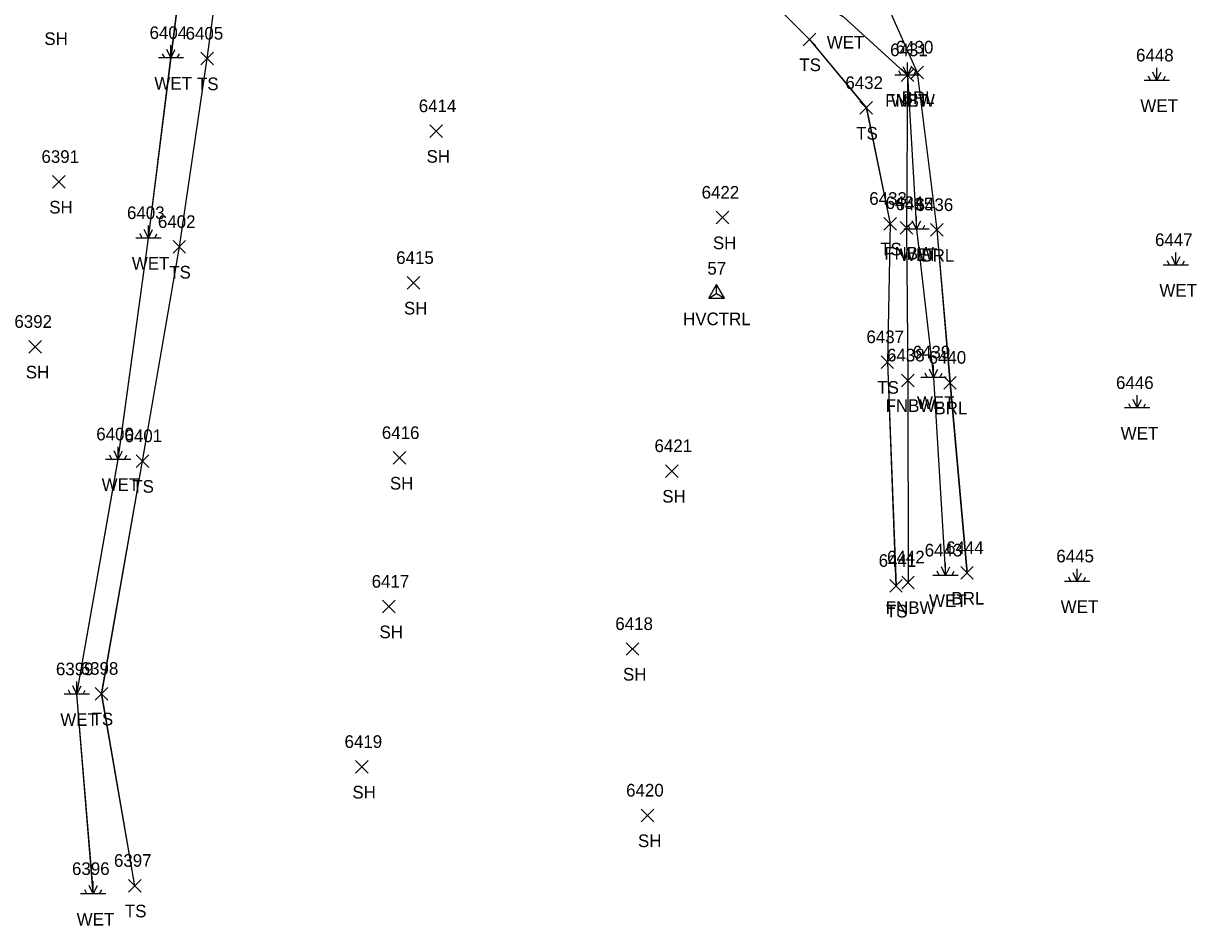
# Model space of a CAD drawing. Extents: x 1554668 to 1563881, y 831386 to 834374.
# Drawn here: x 1563328.7 to 1563514.3, y 833786 to 833928.7 of the extents above; entities that cross this region are included whole.
import ezdxf

# ---------------------------------------------------------------- set-up
doc = ezdxf.new("R2010")
doc.units = 0
for name, color, linetype in [('C_A', 7, 'Continuous'), ('C_I', 7, 'Continuous'), ('CPSM', 7, 'Continuous'), ('L_A', 7, 'Continuous'), ('L_I', 7, 'Continuous'), ('L_TIC', 7, 'Continuous'), ('LABL', 7, 'Continuous'), ('LELB', 7, 'Continuous'), ('LFNC', 7, 'Continuous'), ('LWET', 7, 'Continuous')]:
    doc.layers.add(name, color=color, linetype=linetype)

msp = doc.modelspace()

# ---------------------------------------------------------------- linework, layer by layer
at = {"layer": 'CPSM'}
for p, q in [((1563437.12, 833885.21), (1563438.37, 833887.38)), ((1563439.62, 833885.21), (1563438.37, 833887.38)), ((1563438.37, 833885.93), (1563438.37, 833887.38)), ((1563437.12, 833885.21), (1563438.37, 833885.93)), ((1563438.37, 833885.93), (1563438.37, 833885.93)), ((1563438.37, 833885.93), (1563439.62, 833885.21)), ((1563437.12, 833885.21), (1563439.62, 833885.21))]:
    msp.add_line(p, q, dxfattribs=at)
at = {"layer": 'L_TIC'}
for points in [[(1563452.05, 833925.12), (1563454.05, 833927.12)], [(1563454.05, 833925.12), (1563452.05, 833927.12)], [(1563356.77, 833922.1), (1563358.77, 833924.1)], [(1563358.77, 833922.1), (1563356.77, 833924.1)], [(1563467.56, 833919.48), (1563469.56, 833921.48)], [(1563469.56, 833919.48), (1563467.56, 833921.48)], [(1563469.11, 833919.91), (1563471.11, 833921.91)], [(1563471.11, 833919.91), (1563469.11, 833921.91)], [(1563461.04, 833914.29), (1563463.04, 833916.29)], [(1563463.04, 833914.29), (1563461.04, 833916.29)], [(1563393, 833910.63), (1563395, 833912.63)], [(1563395, 833910.63), (1563393, 833912.63)], [(1563333.32, 833902.6), (1563335.32, 833904.6)], [(1563335.32, 833902.6), (1563333.32, 833904.6)], [(1563438.31, 833896.95), (1563440.31, 833898.95)], [(1563440.31, 833896.95), (1563438.31, 833898.95)], [(1563464.83, 833895.97), (1563466.83, 833897.97)], [(1563466.83, 833895.97), (1563464.83, 833897.97)], [(1563467.41, 833895.31), (1563469.41, 833897.31)], [(1563469.41, 833895.31), (1563467.41, 833897.31)], [(1563472.21, 833894.99), (1563474.21, 833896.99)], [(1563474.21, 833894.99), (1563472.21, 833896.99)], [(1563352.39, 833892.31), (1563354.39, 833894.31)], [(1563354.39, 833892.31), (1563352.39, 833894.31)], [(1563389.43, 833886.62), (1563391.43, 833888.62)], [(1563391.43, 833886.62), (1563389.43, 833888.62)], [(1563329.61, 833876.51), (1563331.61, 833878.51)], [(1563331.61, 833876.51), (1563329.61, 833878.51)], [(1563464.38, 833874.09), (1563466.38, 833876.09)], [(1563466.38, 833874.09), (1563464.38, 833876.09)], [(1563467.63, 833871.2), (1563469.63, 833873.2)], [(1563469.63, 833871.2), (1563467.63, 833873.2)], [(1563474.29, 833870.83), (1563476.29, 833872.83)], [(1563476.29, 833870.83), (1563474.29, 833872.83)], [(1563346.54, 833858.43), (1563348.54, 833860.43)], [(1563348.54, 833858.43), (1563346.54, 833860.43)], [(1563387.21, 833858.93), (1563389.21, 833860.93)], [(1563389.21, 833858.93), (1563387.21, 833860.93)], [(1563430.29, 833856.86), (1563432.29, 833858.86)], [(1563432.29, 833856.86), (1563430.29, 833858.86)], [(1563476.98, 833840.74), (1563478.98, 833842.74)], [(1563478.98, 833840.74), (1563476.98, 833842.74)], [(1563467.65, 833839.25), (1563469.65, 833841.25)], [(1563469.65, 833839.25), (1563467.65, 833841.25)], [(1563465.75, 833838.7), (1563467.75, 833840.7)], [(1563467.75, 833838.7), (1563465.75, 833840.7)], [(1563385.55, 833835.41), (1563387.55, 833837.41)], [(1563387.55, 833835.41), (1563385.55, 833837.41)], [(1563424.09, 833828.71), (1563426.09, 833830.71)], [(1563426.09, 833828.71), (1563424.09, 833830.71)], [(1563340.1, 833821.63), (1563342.1, 833823.63)], [(1563342.1, 833821.63), (1563340.1, 833823.63)], [(1563381.27, 833810.06), (1563383.27, 833812.06)], [(1563383.27, 833810.06), (1563381.27, 833812.06)], [(1563426.45, 833802.37), (1563428.45, 833804.37)], [(1563428.45, 833802.37), (1563426.45, 833804.37)], [(1563345.36, 833791.26), (1563347.36, 833793.26)], [(1563347.36, 833791.26), (1563345.36, 833793.26)]]:
    msp.add_lwpolyline(points, dxfattribs=at)
at = {"layer": 'LABL'}
for points in [[(1563350.35, 833998.03), (1563398.7, 833978.81), (1563444.96, 833951.84), (1563464.22, 833934.09), (1563470.11, 833920.91), (1563473.21, 833895.99), (1563475.29, 833871.83), (1563477.98, 833841.74)], [(1563350.36, 833998.03), (1563398.71, 833978.82), (1563444.97, 833951.85), (1563464.23, 833934.1), (1563470.12, 833920.91), (1563473.22, 833895.99), (1563475.3, 833871.84), (1563477.99, 833841.75)], [(1563350.36, 833998.03), (1563398.71, 833978.82), (1563444.97, 833951.85), (1563464.23, 833934.1), (1563470.12, 833920.91), (1563473.22, 833895.99), (1563475.3, 833871.84), (1563477.99, 833841.75)], [(1563350.36, 833998.03), (1563398.71, 833978.82), (1563444.97, 833951.85), (1563464.23, 833934.1), (1563470.12, 833920.91), (1563473.22, 833895.99), (1563475.3, 833871.84), (1563477.99, 833841.75)]]:
    msp.add_lwpolyline(points, dxfattribs=at)
at = {"layer": 'LELB'}
for points in [[(1563346.36, 833792.26), (1563341.1, 833822.63), (1563347.54, 833859.43), (1563353.39, 833893.31), (1563357.77, 833923.1), (1563361.23, 833948.17), (1563379.2, 833969.49), (1563398.94, 833957.99), (1563444.14, 833935.12), (1563453.05, 833926.12), (1563462.04, 833915.29), (1563465.83, 833896.97), (1563465.38, 833875.09), (1563466.75, 833839.7)], [(1563346.37, 833792.26), (1563341.11, 833822.63), (1563347.56, 833859.44), (1563353.4, 833893.32), (1563357.77, 833923.11), (1563361.24, 833948.17), (1563379.21, 833969.5), (1563398.94, 833957.99), (1563444.14, 833935.13), (1563453.06, 833926.12), (1563462.06, 833915.3), (1563465.84, 833896.97), (1563465.39, 833875.1), (1563466.76, 833839.71)], [(1563346.37, 833792.26), (1563341.11, 833822.63), (1563347.56, 833859.44), (1563353.4, 833893.32), (1563357.77, 833923.11), (1563361.24, 833948.17), (1563379.21, 833969.5), (1563398.94, 833957.99), (1563444.14, 833935.13), (1563453.06, 833926.12), (1563462.06, 833915.3), (1563465.84, 833896.97), (1563465.39, 833875.1), (1563466.76, 833839.71)], [(1563346.37, 833792.26), (1563341.11, 833822.63), (1563347.56, 833859.44), (1563353.4, 833893.32), (1563357.77, 833923.11), (1563361.24, 833948.17), (1563379.21, 833969.5), (1563398.94, 833957.99), (1563444.14, 833935.13), (1563453.06, 833926.12), (1563462.06, 833915.3), (1563465.84, 833896.97), (1563465.39, 833875.1), (1563466.76, 833839.71)]]:
    msp.add_lwpolyline(points, dxfattribs=at)
at = {"layer": 'LFNC'}
for points in [[(1563468.56, 833920.48), (1563468.41, 833896.31), (1563468.63, 833872.2), (1563468.65, 833840.25)], [(1563468.57, 833920.48), (1563468.43, 833896.32), (1563468.64, 833872.21), (1563468.66, 833840.25)], [(1563468.57, 833920.48), (1563468.43, 833896.32), (1563468.64, 833872.21), (1563468.66, 833840.25)], [(1563468.57, 833920.48), (1563468.43, 833896.32), (1563468.64, 833872.21), (1563468.66, 833840.25)]]:
    msp.add_lwpolyline(points, dxfattribs=at)
at = {"layer": 'LWET'}
for p, q in [((1563352.07, 833923.2), (1563351.4, 833924.53)), ((1563352.07, 833923.2), (1563352.07, 833925.2)), ((1563352.07, 833923.2), (1563352.73, 833924.53)), ((1563354.07, 833923.2), (1563350.07, 833923.2)), ((1563351.07, 833923.2), (1563350.73, 833923.87)), ((1563353.07, 833923.2), (1563353.4, 833923.87)), ((1563467.56, 833920.48), (1563467.22, 833921.14)), ((1563468.56, 833920.48), (1563467.89, 833921.81)), ((1563468.56, 833920.48), (1563468.56, 833922.48)), ((1563468.56, 833920.48), (1563469.22, 833921.81)), ((1563469.56, 833920.48), (1563469.89, 833921.14)), ((1563508.02, 833919.65), (1563507.36, 833920.98)), ((1563508.02, 833919.65), (1563508.02, 833921.65)), ((1563508.02, 833919.65), (1563508.69, 833920.98)), ((1563470.56, 833920.48), (1563466.56, 833920.48)), ((1563510.02, 833919.65), (1563506.02, 833919.65)), ((1563507.02, 833919.65), (1563506.69, 833920.32)), ((1563509.02, 833919.65), (1563509.36, 833920.32)), ((1563348.5, 833894.72), (1563348.5, 833896.72)), ((1563468.99, 833896.11), (1563468.66, 833896.77)), ((1563469.99, 833896.11), (1563469.33, 833897.44)), ((1563469.99, 833896.11), (1563469.99, 833898.11)), ((1563469.99, 833896.11), (1563470.66, 833897.44)), ((1563470.99, 833896.11), (1563471.33, 833896.77)), ((1563350.5, 833894.72), (1563346.5, 833894.72)), ((1563347.5, 833894.72), (1563347.17, 833895.38)), ((1563348.5, 833894.72), (1563347.83, 833896.05)), ((1563348.5, 833894.72), (1563349.17, 833896.05)), ((1563349.5, 833894.72), (1563349.83, 833895.38)), ((1563471.99, 833896.11), (1563467.99, 833896.11)), ((1563510.03, 833890.45), (1563509.7, 833891.11)), ((1563511.03, 833890.45), (1563510.36, 833891.78)), ((1563511.03, 833890.45), (1563511.03, 833892.45)), ((1563511.03, 833890.45), (1563511.7, 833891.78)), ((1563512.03, 833890.45), (1563512.36, 833891.11)), ((1563513.03, 833890.45), (1563509.03, 833890.45)), ((1563472.69, 833872.67), (1563472.69, 833874.67)), ((1563474.69, 833872.67), (1563470.69, 833872.67)), ((1563471.69, 833872.67), (1563471.36, 833873.33)), ((1563472.69, 833872.67), (1563472.03, 833874)), ((1563472.69, 833872.67), (1563473.36, 833874)), ((1563473.69, 833872.67), (1563474.03, 833873.33)), ((1563504.91, 833867.84), (1563504.24, 833869.17)), ((1563504.91, 833867.84), (1563504.91, 833869.84)), ((1563504.91, 833867.84), (1563505.58, 833869.17)), ((1563506.91, 833867.84), (1563502.91, 833867.84)), ((1563503.91, 833867.84), (1563503.58, 833868.51)), ((1563505.91, 833867.84), (1563506.24, 833868.51)), ((1563343.72, 833859.71), (1563343.72, 833861.71)), ((1563345.72, 833859.71), (1563341.72, 833859.71)), ((1563342.72, 833859.71), (1563342.39, 833860.38)), ((1563343.72, 833859.71), (1563343.06, 833861.05)), ((1563343.72, 833859.71), (1563344.39, 833861.05)), ((1563344.72, 833859.71), (1563345.06, 833860.38)), ((1563474.59, 833841.35), (1563474.59, 833843.35)), ((1563476.59, 833841.35), (1563472.59, 833841.35)), ((1563473.59, 833841.35), (1563473.26, 833842.02)), ((1563474.59, 833841.35), (1563473.93, 833842.69)), ((1563474.59, 833841.35), (1563475.26, 833842.69)), ((1563475.59, 833841.35), (1563475.93, 833842.02)), ((1563494.42, 833840.41), (1563494.09, 833841.07)), ((1563495.42, 833840.41), (1563494.75, 833841.74)), ((1563495.42, 833840.41), (1563495.42, 833842.41)), ((1563495.42, 833840.41), (1563496.09, 833841.74)), ((1563496.42, 833840.41), (1563496.75, 833841.07)), ((1563497.42, 833840.41), (1563493.42, 833840.41)), ((1563337.18, 833822.55), (1563337.18, 833824.55)), ((1563339.18, 833822.55), (1563335.18, 833822.55)), ((1563336.18, 833822.55), (1563335.85, 833823.22)), ((1563337.18, 833822.55), (1563336.52, 833823.88)), ((1563337.18, 833822.55), (1563337.85, 833823.88)), ((1563338.18, 833822.55), (1563338.52, 833823.22)), ((1563339.78, 833790.96), (1563339.78, 833792.96)), ((1563341.78, 833790.96), (1563337.78, 833790.96)), ((1563338.78, 833790.96), (1563338.44, 833791.63)), ((1563339.78, 833790.96), (1563339.11, 833792.3)), ((1563339.78, 833790.96), (1563340.44, 833792.3)), ((1563340.78, 833790.96), (1563341.11, 833791.63))]:
    msp.add_line(p, q, dxfattribs=at)
for points in [[(1563339.78, 833790.96), (1563337.18, 833822.55), (1563343.72, 833859.71), (1563348.5, 833894.72), (1563352.07, 833923.2), (1563355.46, 833950.06), (1563376.93, 833974.07), (1563399.31, 833964.81), (1563443.75, 833939.01), (1563458.42, 833929.69), (1563468.56, 833920.48), (1563469.99, 833896.11), (1563472.69, 833872.67), (1563474.59, 833841.35)], [(1563339.79, 833790.97), (1563337.19, 833822.56), (1563343.73, 833859.72), (1563348.51, 833894.72), (1563352.08, 833923.21), (1563355.47, 833950.06), (1563376.94, 833974.08), (1563399.32, 833964.82), (1563443.76, 833939.01), (1563458.43, 833929.7), (1563468.57, 833920.48), (1563470, 833896.11), (1563472.7, 833872.67), (1563474.6, 833841.36)], [(1563339.79, 833790.97), (1563337.19, 833822.56), (1563343.73, 833859.72), (1563348.51, 833894.72), (1563352.08, 833923.21), (1563355.47, 833950.06), (1563376.94, 833974.08), (1563399.32, 833964.82), (1563443.76, 833939.01), (1563458.43, 833929.7), (1563468.57, 833920.48), (1563470, 833896.11), (1563472.7, 833872.67), (1563474.6, 833841.36)], [(1563339.79, 833790.97), (1563337.19, 833822.56), (1563343.73, 833859.72), (1563348.51, 833894.72), (1563352.08, 833923.21), (1563355.47, 833950.06), (1563376.94, 833974.08), (1563399.32, 833964.82), (1563443.76, 833939.01), (1563458.43, 833929.7), (1563468.57, 833920.48), (1563470, 833896.11), (1563472.7, 833872.67), (1563474.6, 833841.36)]]:
    msp.add_lwpolyline(points, dxfattribs=at)

# ---------------------------------------------------------------- texts
at = {"layer": 'C_A'}
msp.add_text('HVCTRL', height=2, dxfattribs=at).set_placement((1563433.07, 833880.93))
at = {"layer": 'C_I'}
msp.add_text('57', height=2, dxfattribs=at).set_placement((1563436.91, 833888.93))
at = {"layer": 'L_A'}
for s, p in [('SH', (1563332.04, 833925.25)), ('WET', (1563455.8, 833924.69)), ('TS', (1563451.46, 833921.12)), ('WET', (1563349.44, 833918.2)), ('TS', (1563356.18, 833918.1)), ('FNBW', (1563465.03, 833915.48)), ('WET', (1563465.93, 833915.48)), ('BRL', (1563467.65, 833915.91)), ('WET', (1563505.4, 833914.65)), ('TS', (1563460.45, 833910.29)), ('SH', (1563392.49, 833906.63)), ('SH', (1563332.81, 833898.6)), ('SH', (1563437.79, 833892.95)), ('TS', (1563464.24, 833891.97)), ('FNBW', (1563464.89, 833891.31)), ('WET', (1563467.37, 833891.11)), ('BRL', (1563470.76, 833890.99)), ('WET', (1563345.88, 833889.72)), ('TS', (1563351.8, 833888.31)), ('WET', (1563508.41, 833885.45)), ('SH', (1563388.92, 833882.62)), ('SH', (1563329.1, 833872.51)), ('TS', (1563463.79, 833870.09)), ('FNBW', (1563465.1, 833867.2)), ('WET', (1563470.07, 833867.67)), ('BRL', (1563472.83, 833866.83)), ('WET', (1563502.29, 833862.84)), ('WET', (1563341.1, 833854.71)), ('TS', (1563345.95, 833854.43)), ('SH', (1563386.7, 833854.93)), ('SH', (1563429.78, 833852.86)), ('FNBW', (1563465.12, 833835.25)), ('WET', (1563471.97, 833836.35)), ('BRL', (1563475.52, 833836.74)), ('WET', (1563492.8, 833835.41)), ('TS', (1563465.16, 833834.7)), ('SH', (1563385.04, 833831.41)), ('SH', (1563423.57, 833824.71)), ('WET', (1563334.56, 833817.55)), ('TS', (1563339.51, 833817.63)), ('SH', (1563380.76, 833806.06)), ('SH', (1563425.94, 833798.37)), ('TS', (1563344.77, 833787.26)), ('WET', (1563337.15, 833785.96))]:
    msp.add_text(s, height=2, dxfattribs=at).set_placement(p)
at = {"layer": 'L_I'}
for s, p in [('6404', (1563348.68, 833926.2)), ('6405', (1563354.38, 833926.1)), ('6431', (1563465.82, 833923.48)), ('6431', (1563465.82, 833923.48)), ('6430', (1563466.71, 833923.91)), ('6448', (1563504.72, 833922.65)), ('6432', (1563458.74, 833918.29)), ('6414', (1563391.26, 833914.63)), ('6391', (1563331.58, 833906.6)), ('6422', (1563436, 833900.95)), ('6433', (1563462.52, 833899.97)), ('6434', (1563465.11, 833899.31)), ('6435', (1563466.69, 833899.11)), ('6436', (1563469.85, 833898.99)), ('6403', (1563345.11, 833897.72)), ('6402', (1563350, 833896.31)), ('6447', (1563507.72, 833893.45)), ('6415', (1563387.69, 833890.62)), ('6392', (1563327.3, 833880.51)), ('6437', (1563462.07, 833878.09)), ('6438', (1563465.33, 833875.2)), ('6439', (1563469.38, 833875.67)), ('6440', (1563471.9, 833874.83)), ('6446', (1563501.55, 833870.84)), ('6400', (1563340.25, 833862.71)), ('6401', (1563344.72, 833862.43)), ('6416', (1563385.42, 833862.93)), ('6421', (1563428.55, 833860.86)), ('6444', (1563474.67, 833844.74)), ('6441', (1563464.01, 833842.7)), ('6442', (1563465.34, 833843.25)), ('6443', (1563471.29, 833844.35)), ('6445', (1563492.11, 833843.41)), ('6417', (1563383.81, 833839.41)), ('6418', (1563422.35, 833832.71)), ('6399', (1563333.87, 833825.55)), ('6398', (1563337.79, 833825.63)), ('6419', (1563379.52, 833814.06)), ('6420', (1563424.06, 833806.37)), ('6397', (1563343.05, 833795.26)), ('6396', (1563336.41, 833793.96))]:
    msp.add_text(s, height=2, dxfattribs=at).set_placement(p)

doc.saveas('drawing.dxf')
